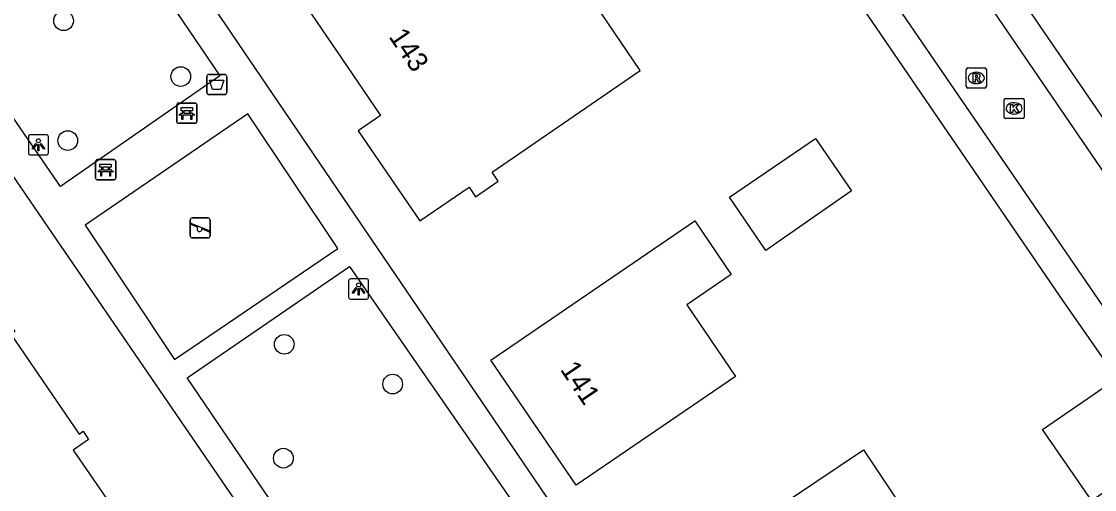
# Model space of a CAD drawing. Extents: x 155275 to 156263, y 382654 to 383635.
# Drawn here: x 155452.4 to 155505.7, y 383344.2 to 383367.5 of the extents above; entities that cross this region are included whole.
import ezdxf

# ---------------------------------------------------------------- set-up
doc = ezdxf.new("R2010")
doc.units = 0
for name, color, linetype in [('IMGEO_Afvalbak', 7, 'Continuous'), ('IMGEO_Bank', 7, 'Continuous'), ('IMGEO_Boom', 7, 'Continuous'), ('IMGEO_Kolk', 7, 'Continuous'), ('IMGEO_Lichtpunt', 7, 'Continuous'), ('IMGEO_Pand', 7, 'Continuous'), ('IMGEO_Pand_nummerreeks', 7, 'Continuous'), ('IMGEO_Rijbaan_lokaal_open', 7, 'Continuous'), ('IMGEO_Rioolput', 7, 'Continuous'), ('IMGEO_Speelvoorziening', 7, 'Continuous'), ('IMGEO_Voetpad_open', 7, 'Continuous')]:
    doc.layers.add(name, color=color, linetype=linetype)

msp = doc.modelspace()

# ---------------------------------------------------------------- linework, layer by layer
at = {"layer": 'IMGEO_Afvalbak'}
for p, q in [((155461.568, 383363.922), (155461.568, 383364.722)), ((155461.568, 383364.722), (155461.568, 383363.922)), ((155461.668, 383364.822), (155462.458, 383364.822)), ((155462.458, 383364.822), (155461.668, 383364.822)), ((155462.558, 383364.722), (155462.558, 383363.922)), ((155462.558, 383363.922), (155462.558, 383364.722)), ((155462.458, 383363.822), (155461.668, 383363.822)), ((155461.668, 383363.822), (155462.458, 383363.822))]:
    msp.add_line(p, q, dxfattribs=at)
msp.add_lwpolyline([(155461.711, 383364.536), (155462.415, 383364.536), (155462.266, 383364.066), (155461.86, 383364.066), (155461.711, 383364.536)], dxfattribs=at)
for centre, start, end in [((155461.668, 383364.722), 90, 180), ((155461.668, 383364.722), 90, 180), ((155462.458, 383364.722), 0, 90), ((155462.458, 383364.722), 360, 90), ((155461.668, 383363.922), 180, 270), ((155461.668, 383363.922), 180, 270), ((155462.458, 383363.922), 270, 0), ((155462.458, 383363.922), 270, 0)]:
    msp.add_arc(centre, 0.1, start, end, dxfattribs=at)
at = {"layer": 'IMGEO_Bank'}
for p, q in [((155460.075, 383362.471), (155460.075, 383363.312)), ((155460.075, 383363.312), (155460.075, 383362.471)), ((155460.15, 383363.396), (155460.991, 383363.396)), ((155460.991, 383363.396), (155460.15, 383363.396)), ((155461.075, 383363.321), (155461.075, 383362.48)), ((155461.075, 383362.48), (155461.075, 383363.321)), ((155460.772, 383362.794), (155460.379, 383362.794)), ((155460.384, 383362.902), (155460.384, 383363.008)), ((155460.428, 383363.008), (155460.428, 383362.902)), ((155460.716, 383363.014), (155460.434, 383363.014)), ((155460.434, 383362.896), (155460.716, 383362.896)), ((155460.722, 383362.902), (155460.722, 383363.008)), ((155460.766, 383363.008), (155460.766, 383362.902)), ((155461, 383362.396), (155460.159, 383362.396)), ((155460.159, 383362.396), (155461, 383362.396)), ((155456.044, 383359.664), (155456.044, 383360.505)), ((155456.044, 383360.505), (155456.044, 383359.664)), ((155456.119, 383360.589), (155456.96, 383360.589)), ((155456.96, 383360.589), (155456.119, 383360.589)), ((155457.044, 383360.514), (155457.044, 383359.673)), ((155457.044, 383359.673), (155457.044, 383360.514)), ((155456.741, 383359.987), (155456.348, 383359.987)), ((155456.353, 383360.095), (155456.353, 383360.201)), ((155456.397, 383360.201), (155456.397, 383360.095)), ((155456.685, 383360.207), (155456.403, 383360.207)), ((155456.403, 383360.089), (155456.685, 383360.089)), ((155456.691, 383360.095), (155456.691, 383360.201)), ((155456.735, 383360.201), (155456.735, 383360.095)), ((155456.969, 383359.589), (155456.128, 383359.589)), ((155456.128, 383359.589), (155456.969, 383359.589))]:
    msp.add_line(p, q, dxfattribs=at)
for points in [[(155460.378, 383363.014), (155460.292, 383363.014), (155460.292, 383363.175), (155460.855, 383363.175), (155460.855, 383363.014), (155460.772, 383363.014)], [(155460.322, 383362.794), (155460.18, 383362.794), (155460.292, 383362.896), (155460.378, 383362.896)], [(155460.372, 383362.787), (155460.372, 383362.58), (155460.329, 383362.58), (155460.329, 383362.787)], [(155460.772, 383362.896), (155460.855, 383362.896), (155460.967, 383362.794), (155460.828, 383362.794)], [(155460.822, 383362.787), (155460.822, 383362.58), (155460.778, 383362.58), (155460.778, 383362.787)], [(155456.291, 383359.987), (155456.149, 383359.987), (155456.261, 383360.089), (155456.347, 383360.089)], [(155456.347, 383360.207), (155456.261, 383360.207), (155456.261, 383360.368), (155456.824, 383360.368), (155456.824, 383360.207), (155456.741, 383360.207)], [(155456.341, 383359.98), (155456.341, 383359.773), (155456.298, 383359.773), (155456.298, 383359.98)], [(155456.741, 383360.089), (155456.824, 383360.089), (155456.936, 383359.987), (155456.797, 383359.987)], [(155456.791, 383359.98), (155456.791, 383359.773), (155456.747, 383359.773), (155456.747, 383359.98)]]:
    msp.add_lwpolyline(points, dxfattribs=at)
for centre, radius, start, end in [((155460.153, 383363.318), 0.0779, 92.4484, 184.2845), ((155460.153, 383363.318), 0.0779, 92.4484, 184.2845), ((155460.997, 383363.318), 0.0779, 2.4484, 94.2845), ((155460.997, 383363.318), 0.0779, 2.4484, 94.2845), ((155460.322, 383362.787), 0.00671, 2.8957, 87.1043), ((155460.379, 383362.787), 0.00671, 92.8957, 177.1043), ((155460.377, 383363.007), 0.00671, 2.8957, 87.1043), ((155460.377, 383362.903), 0.00671, 272.8957, 357.1043), ((155460.434, 383363.007), 0.00671, 92.8957, 177.1043), ((155460.434, 383362.903), 0.00671, 182.8957, 267.1043), ((155460.716, 383363.007), 0.00671, 2.8957, 87.1043), ((155460.716, 383362.903), 0.00671, 272.8957, 357.1043), ((155460.773, 383363.007), 0.00671, 92.8957, 177.1043), ((155460.773, 383362.903), 0.00671, 182.8957, 267.1043), ((155460.771, 383362.787), 0.00671, 2.8957, 87.1043), ((155460.828, 383362.787), 0.00671, 92.8957, 177.1043), ((155460.153, 383362.474), 0.0779, 182.4484, 274.2845), ((155460.153, 383362.474), 0.0779, 182.4484, 274.2845), ((155460.997, 383362.474), 0.0779, 272.4484, 4.2845), ((155460.997, 383362.474), 0.0779, 272.4484, 4.2845), ((155456.122, 383360.511), 0.0779, 92.4484, 184.2845), ((155456.122, 383360.511), 0.0779, 92.4484, 184.2845), ((155456.966, 383360.511), 0.0779, 2.4484, 94.2845), ((155456.966, 383360.511), 0.0779, 2.4484, 94.2845), ((155456.291, 383359.98), 0.00671, 2.8957, 87.1043), ((155456.348, 383359.98), 0.00671, 92.8957, 177.1043), ((155456.346, 383360.2), 0.00671, 2.8957, 87.1043), ((155456.346, 383360.096), 0.00671, 272.8957, 357.1043), ((155456.403, 383360.2), 0.00671, 92.8957, 177.1043), ((155456.403, 383360.096), 0.00671, 182.8957, 267.1043), ((155456.685, 383360.2), 0.00671, 2.8957, 87.1043), ((155456.685, 383360.096), 0.00671, 272.8957, 357.1043), ((155456.742, 383360.2), 0.00671, 92.8957, 177.1043), ((155456.742, 383360.096), 0.00671, 182.8957, 267.1043), ((155456.74, 383359.98), 0.00671, 2.8957, 87.1043), ((155456.797, 383359.98), 0.00671, 92.8957, 177.1043), ((155456.122, 383359.667), 0.0779, 182.4484, 274.2845), ((155456.122, 383359.667), 0.0779, 182.4484, 274.2845), ((155456.966, 383359.667), 0.0779, 272.4484, 4.2845), ((155456.966, 383359.667), 0.0779, 272.4484, 4.2845)]:
    msp.add_arc(centre, radius, start, end, dxfattribs=at)
at = {"layer": 'IMGEO_Boom'}
for centre in [(155454.453, 383367.49), (155460.278, 383364.717), (155454.66, 383361.536), (155465.415, 383351.413), (155470.807, 383349.439), (155465.376, 383345.756)]:
    msp.add_circle(centre, 0.489, dxfattribs=at)
at = {"layer": 'IMGEO_Kolk'}
for p, q in [((155501.265, 383363.633), (155502.117, 383363.633)), ((155501.19, 383362.707), (155501.19, 383363.559)), ((155501.678, 383363.413), (155501.703, 383363.413)), ((155502.191, 383363.559), (155502.191, 383362.707)), ((155502.117, 383362.633), (155501.265, 383362.633)), ((155501.701, 383362.853), (155501.676, 383362.853))]:
    msp.add_line(p, q, dxfattribs=at)
for points in [[(155501.265, 383363.633), (155502.117, 383363.633)], [(155501.19, 383362.707), (155501.19, 383363.559)], [(155501.511, 383363.333), (155501.634, 383363.333), (155501.634, 383363.182), (155501.764, 383363.333), (155501.928, 383363.333), (155501.782, 383363.182), (155501.935, 383362.933), (155501.783, 383362.933), (155501.698, 383363.097), (155501.634, 383363.03), (155501.634, 383362.933), (155501.511, 383362.933), (155501.511, 383363.333)], [(155502.191, 383363.559), (155502.191, 383362.707)], [(155502.117, 383362.633), (155501.265, 383362.633)]]:
    msp.add_lwpolyline(points, dxfattribs=at)
for centre, start, end in [((155501.267, 383363.557), 91.552, 178.448), ((155501.267, 383363.557), 91.552, 178.448), ((155502.115, 383363.557), 1.552, 88.448), ((155502.115, 383363.557), 1.552, 88.448), ((155501.267, 383362.709), 181.552, 268.448), ((155501.267, 383362.709), 181.552, 268.448), ((155502.115, 383362.709), 271.552, 358.448), ((155502.115, 383362.709), 271.552, 358.448)]:
    msp.add_arc(centre, 0.0765, start, end, dxfattribs=at)
for centre, major_axis, ratio, start_param, end_param in [((155501.677, 383363.133), (-0.387, 0.002), 0.722429, 4.712389, 7.853982), ((155501.702, 383363.133), (-0.39, 0.002), 0.717154, 1.570796, 4.712389)]:
    msp.add_ellipse(centre, major_axis=major_axis, ratio=ratio, start_param=start_param, end_param=end_param, dxfattribs=at)
at = {"layer": 'IMGEO_Lichtpunt'}
for p, q in [((155452.703, 383361.729), (155452.703, 383360.922)), ((155452.703, 383361.729), (155452.703, 383360.922)), ((155453.605, 383361.824), (155452.797, 383361.824)), ((155453.605, 383361.824), (155452.797, 383361.824)), ((155453.699, 383360.922), (155453.699, 383361.729)), ((155453.699, 383360.922), (155453.699, 383361.729)), ((155452.797, 383360.828), (155453.605, 383360.828)), ((155452.797, 383360.828), (155453.605, 383360.828)), ((155468.614, 383354.564), (155468.614, 383353.757)), ((155468.614, 383354.564), (155468.614, 383353.757)), ((155469.516, 383354.659), (155468.708, 383354.659)), ((155469.516, 383354.659), (155468.708, 383354.659)), ((155469.61, 383353.757), (155469.61, 383354.564)), ((155469.61, 383353.757), (155469.61, 383354.564)), ((155468.708, 383353.663), (155469.516, 383353.663)), ((155468.708, 383353.663), (155469.516, 383353.663))]:
    msp.add_line(p, q, dxfattribs=at)
for points in [[(155453.077, 383361.393), (155453.116, 383361.365), (155452.928, 383361.103), (155452.89, 383361.13), (155453.077, 383361.393)], [(155453.179, 383361.345), (155453.226, 383361.345), (155453.226, 383361.023), (155453.179, 383361.023), (155453.179, 383361.345)], [(155453.289, 383361.365), (155453.327, 383361.392), (155453.514, 383361.13), (155453.475, 383361.102), (155453.289, 383361.365)], [(155468.988, 383354.228), (155469.027, 383354.2), (155468.839, 383353.938), (155468.801, 383353.965), (155468.988, 383354.228)], [(155469.09, 383354.18), (155469.137, 383354.18), (155469.137, 383353.858), (155469.09, 383353.858), (155469.09, 383354.18)], [(155469.2, 383354.2), (155469.238, 383354.227), (155469.425, 383353.965), (155469.386, 383353.937), (155469.2, 383354.2)]]:
    msp.add_lwpolyline(points, dxfattribs=at)
for centre in [(155453.202, 383361.527), (155469.113, 383354.362)]:
    msp.add_circle(centre, 0.0994, dxfattribs=at)
for centre, start, end in [((155452.797, 383361.729), 90, 180), ((155452.797, 383361.729), 90, 180), ((155453.605, 383361.729), 0, 90), ((155453.605, 383361.729), 0, 90), ((155452.797, 383360.922), 180, 270), ((155452.797, 383360.922), 180, 270), ((155453.605, 383360.922), 270, 0), ((155453.605, 383360.922), 270, 360), ((155468.708, 383354.564), 90, 180), ((155468.708, 383354.564), 90, 180), ((155469.516, 383354.564), 0, 90), ((155469.516, 383354.564), 0, 90), ((155468.708, 383353.757), 180, 270), ((155468.708, 383353.757), 180, 270), ((155469.516, 383353.757), 270, 0), ((155469.516, 383353.757), 270, 360)]:
    msp.add_arc(centre, 0.0946, start, end, dxfattribs=at)
at = {"layer": 'IMGEO_Pand'}
for points in [[(155489.159, 383375.327), (155486.299, 383379.449), (155474.54, 383371.364), (155473.411, 383372.99), (155471.335, 383371.562), (155471.198, 383371.76), (155469.733, 383370.752), (155469.902, 383370.504), (155466.523, 383368.181), (155468.257, 383365.636), (155470.207, 383362.774), (155469.1, 383362.019), (155472.152, 383357.54), (155474.61, 383359.215), (155474.928, 383358.748), (155476.052, 383359.514), (155475.743, 383359.968), (155483.105, 383365.017), (155480.236, 383369.25), (155489.159, 383375.327)], [(155493.601, 383359.037), (155489.347, 383356.079), (155487.548, 383358.725), (155491.812, 383361.634), (155493.601, 383359.037)], [(155485.82, 383357.55), (155487.63, 383354.886), (155485.419, 383353.377), (155487.845, 383349.822), (155479.933, 383344.421), (155475.693, 383350.632), (155485.82, 383357.55)], [(155440.523, 383344.13), (155441.34, 383344.675), (155441.067, 383345.1), (155445.065, 383347.851), (155444.806, 383348.276), (155447.463, 383350.102), (155447.754, 383349.697), (155451.766, 383352.44), (155452.035, 383352.043), (155451.835, 383351.909), (155455.223, 383346.955), (155455.421, 383347.09), (155455.698, 383346.686), (155454.929, 383346.157), (155457.104, 383343.005), (155447.203, 383336.173), (155445.018, 383339.34), (155444.742, 383339.74), (155443.903, 383339.191), (155440.523, 383344.13)], [(155507.508, 383345.001), (155507.473, 383344.976), (155505.556, 383343.643), (155503.094, 383347.184), (155506.697, 383349.656), (155508.02, 383347.727)], [(155499.623, 383339.712), (155493.84, 383335.845), (155493.247, 383336.716), (155490.985, 383335.2), (155487.602, 383332.925), (155483.522, 383339.002), (155494.198, 383346.171), (155496.364, 383342.946), (155497.122, 383343.453), (155499.623, 383339.712)]]:
    msp.add_lwpolyline(points, dxfattribs=at)
at = {"layer": 'IMGEO_Rijbaan_lokaal_open'}
msp.add_lwpolyline([(155512.166, 383351.178), (155472.047, 383409.844), (155468.778, 383407.739), (155509.012, 383349.048)], dxfattribs=at)
at = {"layer": 'IMGEO_Rioolput'}
for p, q in [((155499.309, 383364.221), (155499.309, 383365.073)), ((155499.384, 383365.147), (155500.236, 383365.147)), ((155499.797, 383364.927), (155499.822, 383364.927)), ((155500.31, 383365.073), (155500.31, 383364.221)), ((155500.236, 383364.147), (155499.384, 383364.147)), ((155499.82, 383364.367), (155499.795, 383364.367))]:
    msp.add_line(p, q, dxfattribs=at)
for points in [[(155499.309, 383364.221), (155499.309, 383365.073)], [(155499.384, 383365.147), (155500.236, 383365.147)], [(155499.898, 383364.845), (155499.646, 383364.847), (155499.646, 383364.447)], [(155499.824, 383364.766), (155499.77, 383364.766), (155499.77, 383364.685)], [(155499.77, 383364.685), (155499.822, 383364.685)], [(155500.31, 383365.073), (155500.31, 383364.221)], [(155500.236, 383364.147), (155499.384, 383364.147)], [(155499.646, 383364.447), (155499.77, 383364.447), (155499.77, 383364.609), (155499.781, 383364.609)], [(155499.828, 383364.58), (155499.899, 383364.447), (155500.039, 383364.447), (155499.974, 383364.573)]]:
    msp.add_lwpolyline(points, dxfattribs=at)
for centre, radius, start, end in [((155499.386, 383365.071), 0.0765, 91.552, 178.448), ((155499.386, 383365.071), 0.0765, 91.552, 178.448), ((155499.806, 383364.874), 0.19, 274.7715, 282.9687), ((155499.83, 383364.67), 0.0964, 77.0061, 93.1865), ((155499.844, 383364.727), 0.0378, 276.6634, 79.6772), ((155499.897, 383364.735), 0.109, 350.3612, 89.416), ((155499.895, 383364.735), 0.112, 277.5842, 350.9817), ((155500.234, 383365.071), 0.0765, 1.552, 88.448), ((155500.234, 383365.071), 0.0765, 1.552, 88.448), ((155499.386, 383364.223), 0.0765, 181.552, 268.448), ((155499.386, 383364.223), 0.0765, 181.552, 268.448), ((155499.78, 383364.556), 0.0533, 26.0293, 88.6989), ((155499.879, 383364.52), 0.108, 29.5134, 73.7905), ((155500.234, 383364.223), 0.0765, 271.552, 358.448), ((155500.234, 383364.223), 0.0765, 271.552, 358.448)]:
    msp.add_arc(centre, radius, start, end, dxfattribs=at)
for centre, major_axis, ratio, start_param, end_param in [((155499.796, 383364.647), (-0.387, 0.002), 0.722429, 4.712389, 7.853982), ((155499.821, 383364.647), (-0.39, 0.002), 0.717154, 1.570796, 4.712389)]:
    msp.add_ellipse(centre, major_axis=major_axis, ratio=ratio, start_param=start_param, end_param=end_param, dxfattribs=at)
at = {"layer": 'IMGEO_Speelvoorziening'}
for p, q in [((155460.746, 383356.796), (155460.746, 383357.596)), ((155460.746, 383357.596), (155460.746, 383356.796)), ((155461.129, 383357.224), (155460.79, 383357.361)), ((155460.815, 383357.421), (155461.691, 383357.068)), ((155460.846, 383357.696), (155461.636, 383357.696)), ((155461.636, 383357.696), (155460.846, 383357.696)), ((155461.736, 383357.596), (155461.736, 383356.796)), ((155461.736, 383356.796), (155461.736, 383357.596)), ((155461.636, 383356.696), (155460.846, 383356.696)), ((155460.846, 383356.696), (155461.636, 383356.696)), ((155461.667, 383357.008), (155461.327, 383357.145))]:
    msp.add_line(p, q, dxfattribs=at)
for centre, radius, start, end in [((155460.846, 383357.596), 0.1, 90, 180), ((155460.846, 383357.596), 0.1, 90, 180), ((155460.803, 383357.391), 0.0327, 68.078, 248.078), ((155461.208, 383357.134), 0.12, 130.9928, 5.1632), ((155461.636, 383357.596), 0.1, 0, 90), ((155461.636, 383357.596), 0.1, 360, 90), ((155460.846, 383356.796), 0.1, 180, 270), ((155460.846, 383356.796), 0.1, 180, 270), ((155461.636, 383356.796), 0.1, 270, 0), ((155461.636, 383356.796), 0.1, 270, 0), ((155461.679, 383357.038), 0.0327, 248.078, 68.078)]:
    msp.add_arc(centre, radius, start, end, dxfattribs=at)
at = {"layer": 'IMGEO_Voetpad_open'}
for points in [[(155508.176, 383347.775), (155504.161, 383353.523), (155466.928, 383407.999), (155472.381, 383411.861), (155512.708, 383353.008), (155513.593, 383351.746)], [(155439.322, 383401.258), (155440.503, 383399.413), (155458.765, 383372.788), (155486.531, 383331.928), (155487.116, 383331.079)], [(155438.331, 383399.931), (155462.212, 383364.757), (155454.299, 383359.262), (155432.477, 383390.964)], [(155476.546, 383323.803), (155475.264, 383325.741), (155453.901, 383356.913), (155432.169, 383388.701), (155431.582, 383389.599)], [(155463.604, 383362.864), (155455.522, 383357.331), (155459.969, 383350.655), (155468.08, 383356.179), (155463.604, 383362.864)], [(155477.689, 383324.618), (155476.367, 383326.551), (155460.597, 383349.744), (155468.656, 383355.272), (155471.97, 383350.495), (155484.687, 383332.167), (155486.004, 383330.281)]]:
    msp.add_lwpolyline(points, dxfattribs=at)

# ---------------------------------------------------------------- texts
at = {"layer": 'IMGEO_Pand_nummerreeks'}
for s, rotation, p in [('143', 304.2684, (155470.583, 383366.698)), ('141', 303.9882, (155479.102, 383350.162))]:
    msp.add_text(s, height=1, rotation=rotation, dxfattribs=at).set_placement(p)

doc.saveas('drawing.dxf')
